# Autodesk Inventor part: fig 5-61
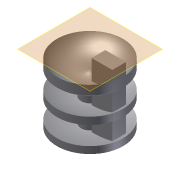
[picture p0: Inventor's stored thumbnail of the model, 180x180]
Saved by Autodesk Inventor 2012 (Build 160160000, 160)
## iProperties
Created: 2004-05
Part Number: fig 5-61
Document SubType Name: Modeling
Designer: CADCIM Technologies
Manufacturer: Standard
Standards Organization: Custom
Density: 1 g/cm^3
Material: Default
Author: CADCIM Technologies
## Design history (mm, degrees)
sketch "Sketch1"
  geometry: L1 (0.098, 22.743)-(0.098, 0.516); L2 (-3.621, 19.305)-(-3.621, 13.061); L3 (-3.621, 10.379)-(-3.621, 3.25); L4 (-3.664, 0.516)-(0.098, 0.516); L5 (-13.694, 4.7)-(-13.694, 1.836); L6 (-13.694, 26.851)-(-13.694, 23.014); L7 (-13.694, 15.335)-(-13.694, 12.343); A1 r 10.546 centre (-4.597, 32.185) between (-13.694, 26.851) and (0.098, 22.743); A2 r 21.828 centre (-4.597, 32.185) between (-13.694, 12.343) and (-3.621, 10.379); A3 r 12.918 centre (-4.597, 32.185) between (-13.694, 23.014) and (-3.621, 19.305); A4 r 19.149 centre (-4.597, 32.185) between (-13.694, 15.335) and (-3.621, 13.061); A5 r 28.952 centre (-4.597, 32.185) between (-13.694, 4.7) and (-3.621, 3.25); A6 r 31.683 centre (-4.597, 32.185) between (-13.694, 1.836) and (-3.664, 0.516)
  constraints: 14 end point, 12 point on circle, 6 centre point, 4 perpendicular, 2 parallel, 1 vertical
revolve "Revolution1" sketch "Sketch1" stored, may be unused: angle "d0" = 90 deg
workplane "Work Plane1"
sketch "Sketch2"
  geometry: L1 (3.408, -2.846)-(12.06, -2.846); L2 (12.06, -2.846)-(12.06, 2.873); L3 (12.06, 2.873)-(3.408, 2.873); L4 (3.408, 2.873)-(3.408, -2.846)
  constraints: 8 end point, 2 parallel, 1 horizontal, 1 perpendicular
extrude "Extrusion3" join sketch "Sketch2" stored distance "d8" = 10; taper "d9" = 0 deg
body "Solid1"
